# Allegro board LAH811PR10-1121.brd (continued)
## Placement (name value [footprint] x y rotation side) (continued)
R246  150_0201_1%  [R_0201]  100.42 74.4 270 top
R247  0_0201_5%  [R0201_0OHM]  88.25 73.82 90 top
R249  0_0201_5%  [R_0201]  109.69 69.04 270 top
R257  0_0201_5%  [R_0201]  102.15 73.47 90 bottom
R260  0_0201_5%  [R_0201]  98.52 74.4 270 top
R261  1.5K_0201_5%  [R_0201]  99.25 75.13 180 top
R267  1K_0201_5%  [R_0201]  101.56 74.06 270 bottom
R270  1K_0201_5%  [R_0201]  87.82 61.94 90 bottom
R271  75_0201_1%  [R_0201]  194.78 19.96 0 bottom
R272  330K_0201_1%  [R_0201]  226.47 15.79 180 bottom
R273  0_0201_5%  [R0201_0OHM]  226.58 15.21 180 bottom
R274  10K_0201_5%  [R_0201]  107.02 61.37 90 top
R283  1M_0201_5%  [R_0201]  225.97 13.94 90 bottom
R288  100K_0201_5%  [R_0201]  125.97 63.49 90 top
R300  0_0201_5%  [R0201_0OHM]  87.67 73.82 90 top
R311  1K_0201_5%  [R_0201]  103.26 73.47 90 bottom
R312  0_0201_5%  [R0201_0OHM]  90.51 63.23 270 top
R322  100K_0201_5%  [R_0201]  200.4 9.98 90 bottom
R335  0_0201_5%  [R_0201]  93.05 62.64 90 top
R374  100K_0201_5%  [R_0201]  183.73 41.69 90 top
R375  100K_0201_5%  [R_0201]  184.37 41.69 90 top
R390  0_0402_5%  [R_0402]  261.18 42.51 90 bottom
R410  100K_0201_5%  [R_0201]  92.75 59.96 90 bottom
R441  0_0603_5%  [R0603_0OHM]  192.95 40.15 180 bottom
R466  1K_0201_5%  [R_0201]  103.28 65.98 0 bottom
R529  75K_0201_5%  [R_0201]  162.14 6.67 270 top
R530  200_0201_1%  [R_0201]  253.84 23.72 270 bottom
R531  200_0201_1%  [R_0201]  251.93 24.86 180 bottom
R532  75K_0201_5%  [R_0201]  163.82 6.06 90 top
R533  0_0201_5%  [R0201_0OHM]  202.49 14.49 270 bottom
R534  0_0201_5%  [R_0201]  163.67 7.56 0 top
R544  0_0201_5%  [R_0201]  91.15 63.23 270 top
R545  0_0201_5%  [R_0201]  91.15 61.96 270 top
R600  10K_0201_5%  [R_0201]  254.6 50.11 90 bottom
R614  51_0201_5%  [R_0201]  130.9 55.9 90 top
R616  100K_0201_5%  [R_0201]  201.28 11.45 0 bottom
R617  20K_0201_5%  [R_0201]  200.67 11.45 180 bottom
R621  10K_0201_5%  [R_0201]  109.49 70.31 270 bottom
R622  10K_0201_5%  [R_0201]  112.92 68.01 0 bottom
R623  200K_0201_5%  [R_0201]  115.53 68.39 270 bottom
R624  200K_0201_5%  [R_0201]  109.79 68.52 270 bottom
R626  0_0402_5%  [R_0402]  183.1 37.41 315 top
R627  47K_0201_5%  [R_0201]  110.33 69.11 180 bottom
R628  47K_0201_5%  [R_0201]  110.38 68.52 270 bottom
R629  100K_0201_5%  [R_0201]  188.41 3.22 270 top
R633  0_0201_5%  [R0201_0OHM]  90.07 72.94 180 bottom
R634  0_0402_5%  [R_0402]  187.54 45.28 90 top
R638  0_0402_5%  [R0402_0OHM]  260.39 43.43 270 bottom
R644  0_0201_5%  [R_0201]  99.15 74.4 270 top
R648  33_0201_5%  [R_0201]  182.21 30.93 90 bottom
R649  10K_0201_5%  [R_0201]  183.35 41.6 180 bottom
R651  0_0201_5%  [R0201_0OHM]  113.17 70.96 180 bottom
R652  0_0201_5%  [R0201_0OHM]  110.95 66.35 45 bottom
R655  0_0402_5%  [R_0402]  186.78 45.28 90 top
R656  10K_0201_5%  [R_0201]  189.18 37.86 0 bottom
R658  100K_0201_5%  [R_0201]  113.74 70.4 180 bottom
R660  51_0201_5%  [R_0201]  131.66 55.95 90 top
R666  100K_0201_5%  [R_0201]  18.51 43.5 270 bottom
R667  100K_0201_5%  [R_0201]  19.14 43.5 270 bottom
R669  0_0603_5%  [R0603_0OHM]  20.66 38.42 180 bottom
R670  0_0603_5%  [R0603_0OHM]  225.97 17.26 0 bottom
R672  0_0201_5%  [R0201_0OHM]  104.38 68.76 270 bottom
R677  1M_0201_5%  [R_0201]  111.98 71.57 180 bottom
R687  0_0402_5%  [R_0402]  184.56 36.9 90 bottom
R688  0_0402_5%  [R_0402]  184.65 46.45 270 bottom
R700  49.9_0201_1%  [R_0201]  186.91 36.45 270 bottom
R701  49.9_0201_1%  [R_0201]  190.97 36.52 180 bottom
R702  0_0201_5%  [R0201_0OHM]  187.8 37.28 90 bottom
R703  49.9_0201_1%  [R_0201]  181.6 31.31 180 bottom
R704  10K_0201_5%  [R_0201]  187.59 46.78 90 bottom
R716  0_0805_5%  [R0805_0OHM]  255.49 56.08 90 bottom
R725  0_0201_5%  [R_0201]  102.71 74.67 90 bottom
R726  0_0201_5%  [R_0201]  103.26 74.67 90 bottom
R747  0_0201_5%  [R0201_0OHM]  187.62 46.14 270 bottom
R789  150_0201_1%  [R_0201]  218.63 13.45 180 bottom
R800  0_0201_5%  [R0201_0OHM]  272.1 42.51 0 bottom
R801  0_0201_5%  [R_0201]  272.68 43.15 180 bottom
R808  0_0201_5%  [R0201_0OHM]  255.64 37.99 180 bottom
R931  2.1K_0402_1%  [R_0402]  92.42 68.32 180 bottom
R932  2.1K_0402_1%  [R_0402]  92.42 67.53 180 bottom
R1015  0_0201_5%  [R0201_0OHM]  128.36 63.57 90 top
R1016  0_0201_5%  [R0201_0OHM]  129 63.57 90 top
R2745  100K_0201_1%  [R_0201]  199.01 24.33 180 bottom
R2751  0_0402_5%  [R_0402]  195.54 27.7 270 bottom
R5717  0_0603_5%  [R_0603]  183.53 39.4 270 bottom
R5768  10K_0402_5%  [R_0402]  199.99 24.15 270 bottom
R5769  1M_0402_5%~D  [R_0402]  201 20.44 90 bottom
R5779  0_0402_5%  [R0402_0OHM]  199.05 22.67 180 bottom
R5867  270K_0402_5%  [R_0402]  183.38 70.53 90 bottom
R5868  47K_0402_5%  [R_0402]  177.15 68.23 225 bottom
R6048  0_0603_5%  [R0603_0OHM]  185.64 48.52 90 top
R6089  0_0402_5%  [R0402_0OHM]  7.28 42.06 0 bottom
R6090  0_0402_5%  [R0402_0OHM]  7.28 42.88 0 bottom
R6116  0_0201_5%  [R0201_0OHM]  163.67 62.93 90 top
R6117  0_0201_5%  [R0201_0OHM]  163.03 62.93 90 top
R6118  0_0201_5%  [R0201_0OHM]  159.09 61.08 90 bottom
R6137  100K_0201_5%  [R_0201]  202.51 15.16 180 bottom
R6143  1K_0201_5%  [R_0201]  89.88 61.37 90 top
R6157  10K_0201_5%  [R_0201]  159.75 61.51 0 bottom
R6161  0_0603_5%  [R0603_0OHM]  186.88 48.4 135 bottom
R6162  10K_0201_5%  [R_0201]  192.27 45.78 90 bottom
R6163  0_0201_5%  [R0201_0OHM]  191.61 46.7 45 bottom
R6168  0_0201_5%  [R_0201]  103.14 67.77 90 bottom
R6169  0_0201_5%  [R0201_0OHM]  120.79 3.37 270 top
R6170  0_0201_5%  [R0201_0OHM]  197.51 37.43 90 bottom
R6171  0_0201_5%  [R_0201]  19.78 43.5 270 bottom
R6172  4.7K_0201_5%  [R_0201]  167.98 51.63 270 top
R6174  4.7K_0201_5%  [R_0201]  176.78 43.11 180 top
R6181  0_0201_5%  [R0201_0OHM]  26.13 3.12 0 bottom
R6182  0_0603_5%  [R0603_0OHM]  31.62 2.08 0 bottom
R6194  100K_0201_5%  [R_0201]  103.79 67.56 0 bottom
R6199  0_0201_5%  [R0201_0OHM]  220.52 17.39 0 bottom
R6204  100K_0201_5%  [R_0201]  101.89 68.07 90 bottom
R6208  0_0201_5%  [R0201_0OHM]  158.33 61.08 90 bottom
R6211  0_0201_5%  [R0201_0OHM]  209.07 3.68 0 bottom
R6212  100K_0201_5%  [R_0201]  210.43 3.33 90 bottom
R6213  0_0603_5%  [R0603_0OHM]  211.35 9.85 180 bottom
R6214  10K_0201_1%  [R_0201]  205.31 11.78 0 bottom
R6215  2.2K_0201_1%  [R_0201]  196.51 1.59 90 bottom
R6216  2.2K_0201_1%  [R_0201]  196.51 3.38 270 bottom
R6217  4.7K_0201_1%  [R_0201]  195.82 4.96 0 bottom
R6218  4.7K_0201_1%  [R_0201]  196.41 5.85 0 bottom
R6219  0_0201_5%  [R0201_0OHM]  195.35 2.2 0 bottom
R6220  0_0201_5%  [R0201_0OHM]  195.35 2.77 0 bottom
R6222  0_0201_5%  [R_0201]  119.72 5.02 180 top
R6223  0_0201_5%  [R_0201]  166.51 61.07 90 top
R6224  0_0201_5%  [R_0201]  167.12 61.07 90 top
R6225  0_0402_5%  [R_0402]  5.53 41.24 270 top
R6226  0_0402_5%  [R_0402]  5.53 42 90 top
R6227  0_0603_5%  [R0603_0OHM]  233.8 3.12 270 top
R6229  0_0201_5%  [R_0201]  167.78 3.22 90 top
RA1  2.2K_0201_5%  [R_0201]  260.95 67.12 180 top
RA2  2.2K_0201_5%  [R_0201]  262.09 67.51 180 bottom
RA3  20_0201_1%  [R_0201]  262.98 66.24 90 bottom
RA6  20_0201_1%  [R_0201]  262.35 65.22 0 bottom
RA8  1K_0201_5%  [R_0201]  261.33 59.89 90 bottom
RA9  1K_0201_5%  [R_0201]  261.33 62.43 90 bottom
RA10  100K_0201_5%  [R_0201]  255.51 65.35 270 top
RA13  100K_0201_1%  [R_0201]  256.12 57.98 180 top
RA14  200K _0201_1%  [R_0201]  277.72 69.33 180 bottom
RA17  0_0201_5%  [R_0201]  265.39 58.88 270 top
RA21  1K_0201_5%  [R_0201]  265.77 57.07 90 top
RA22  0_0402_5%  [R0402_0OHM]  264.5 61.41 90 bottom
RA23  0_0402_5%  [R0402_0OHM]  269.09 69.47 180 bottom
RA25  0_0402_5%  [R0402_0OHM]  265.39 61.41 90 bottom
RA27  0_0201_5%  [R0201_0OHM]  261.33 61.16 90 bottom
RA28  0_0201_5%  [R0201_0OHM]  261.96 62.43 90 bottom
RA30  1K_0201_5%  [R_0201]  260.69 62.81 270 bottom
RA36  0_0402_5%  [R0402_0OHM]  257.24 54.78 90 top
RA41  0_0402_5%  [R0402_0OHM]  266.87 57.5 90 top
RA57  1K_0201_5%  [R_0201]  257.39 56.46 90 top
RA58  0_0201_5%  [R0201_0OHM]  259.42 56.71 90 top
RA62  22_0201_5%  [R_0201]  260.06 56.71 90 top
RA63  100K_0201_5%  [R_0201]  256.76 56.46 90 top
RA64  10K_0201_5%  [R_0201]  258.79 66.36 90 top
RA71  2.2K_0201_5%  [R_0201]  275.65 34.89 180 top
RA72  2.2K_0201_5%  [R_0201]  275.65 34.26 180 top
RA73  0_0603_5%  [R0603_0OHM]  27.59 27.88 0 top
RA74  0_0603_5%  [R0603_0OHM]  274.66 37.34 90 top
RA75  33_0201_5%  [R_0201]  263.87 57.22 270 top
RA76  33_0201_5%  [R_0201]  263.23 57.22 270 top
RA77  33_0201_5%  [R_0201]  262.6 57.22 270 top
RA78  33_0201_5%  [R_0201]  261.96 55.95 270 top
RA79  4.7K_0201_5%  [R_0201]  26.38 19.5 180 top
RA80  4.7K_0201_5%  [R_0201]  275.65 33.62 180 top
RA81  0_0402_5%  [R_0402]  255.11 59.25 0 bottom
RA82  470_0201_1%  [R_0201]  275.65 32.99 180 top
RA83  4.7K_0201_5%  [R_0201]  27.01 20.48 90 top
RA84  0_0402_5%  [R_0402]  264.53 57.32 270 top
RC1  150_0201_1%  [R_0201]  141.33 61.09 0 bottom
RC2  49.9_0201_1%  [R_0201]  133.5 55.76 90 top
RC3  150_0201_1%  [R_0201]  129.49 58.65 270 top
RC8  100_0201_1%  [R_0201]  118.97 58.91 180 bottom
RC12  100_0201_1%  [R_0201]  125.3 33.25 270 bottom
RC13  100_0201_1%  [R_0201]  125.94 33.25 270 bottom
RC14  100_0201_1%  [R_0201]  123.53 32.33 0 bottom
RC15  150_0201_1%  [R_0201]  168.7 37.53 0 top
RC16  200_0201_1%  [R_0201]  160.61 41.17 90 top
RC17  200_0201_1%  [R_0201]  169.46 46.54 0 top
RC20  200_0201_1%  [R_0201]  156.04 38.2 270 top
RC21  10K_0402_5%  [R_0402]  168.97 8.83 0 top
RC120  0_0603_5%  [R_0603]  175.41 47.5 0 bottom
RC139  0_0603_5%  [R0603_0OHM]  170.47 7.82 180 top
RC145  51_0201_5%  [R_0201]  128.87 57.35 0 top
RC146  51_0201_5%  [R_0201]  125.98 56.21 180 top
RC147  100K_0201_5%  [R_0201]  175.73 53.19 270 top
RC150  100_0201_5%  [R_0201]  128.1 61.06 90 bottom
RC151  51_0201_5%  [R_0201]  127.53 61.06 90 bottom
RC165  0_0402_5%  [R0402_0OHM]  177.32 44.89 180 bottom
RC168  0_0402_5%  [R_0402]  177.32 44.13 180 bottom
RC180  51_0201_5%  [R_0201]  129.49 56.49 270 top
RC181  51_0201_5%  [R_0201]  129.82 61.64 180 bottom
RC201  51_0201_5%  [R_0201]  128.22 56.49 270 top
RC202  100_0201_5%  [R_0201]  125.81 61.06 90 bottom
RC203  51_0201_5%  [R_0201]  128.66 61.05 90 bottom
RC222  49.9K_0201_1%  [R_0201]  172.89 49.72 0 bottom
RC223  49.9K_0201_1%  [R_0201]  172.89 48.58 0 bottom
RC226  0_0201_5%  [R0201_0OHM]  141.29 67.7 180 bottom
RC244  10K_0201_5%  [R_0201]  173.74 57.35 180 top
RC247  1K_0201_5%  [R_0201]  107.02 65.35 270 bottom
RC254  0_0201_5%  [R_0201]  154.69 35.46 90 top
RC255  0_0201_5%  [R0201_0OHM]  155.25 35.84 90 top
RC336  10_0201_1%  [R_0201]  159.31 33.12 270 bottom
RC338  10K_0201_5%  [R_0201]  155.96 35.83 90 top
RC339  10K_0201_5%  [R_0201]  154.13 35.46 90 top
RC344  51_0201_5%  [R_0201]  128.2 58.61 0 top
RC351  0_0201_5%  [R_0201]  142.93 62.92 0 bottom
RC367  10_0201_1%  [R_0201]  157.64 33.12 270 bottom
RC368  10_0201_1%  [R_0201]  158.2 33.12 270 bottom
RC369  10_0201_1%  [R_0201]  158.76 33.12 270 bottom
RC430  0_0201_5%  [R0201_0OHM]  173.19 55.44 90 top
RC432  1K_0201_5%  [R_0201]  173.74 56.71 180 top
RC433  8.2K_0201_5%  [R_0201]  170.02 56.08 270 top
RC434  8.2K_0201_5%  [R_0201]  170.02 54.3 90 top
RC503  22_0201_1%  [R_0201]  253.63 10.83 90 top
RC504  22_0201_1%  [R_0201]  257 10.81 0 top
RC505  0_0402_5%  [R0402_0OHM]  174.28 29.53 180 bottom
RC508  1M_0201_5%  [R_0201]  172.68 29.57 270 bottom
RC569  49.9_0201_1%  [R_0201]  158.45 33.25 90 top
RC582  0_0402_5%  [R_0402]  173.94 46.61 180 top
RC583  0_0402_5%  [R0402_0OHM]  172.1 46.99 270 top
RC587  0_0603_5%  [R_0603]  177.95 50.16 270 bottom
RC589  0.1_0402_1%  [R_0402]  174.45 47.74 270 bottom
RC592  0_0603_5%  [R0603_0OHM]  154.01 62.93 0 top
RC595  100K_0201_5%  [R_0201]  166.36 52.13 180 top
RC601  0_0201_5%  [R0201_0OHM]  114.52 58.11 0 bottom
RC602  56_0201_5%  [R_0201]  112.99 58.11 0 bottom
RC603  0_0201_5%  [R0201_0OHM]  114.52 57.47 0 bottom
RC604  100_0201_1%  [R_0201]  113 57.47 0 bottom
RC605  0_0201_5%  [R0201_0OHM]  114.52 58.74 0 bottom
RC606  100_0201_5%  [R_0201]  113 58.74 0 bottom
RC609  10K_0201_5%  [R_0201]  180.3 42.05 180 bottom
RC610  10K_0201_5%  [R_0201]  180.3 41.42 180 bottom
RC611  10K_0201_5%  [R_0201]  180.3 42.72 180 bottom
RC612  10K_0201_5%  [R_0201]  180.3 40.71 180 bottom
RC614  499_0201_1%  [R_0201]  121.93 56.46 0 top
RC615  100K_0201_5%  [R_0201]  180.76 51.12 180 bottom
RC616  100K_0201_5%  [R_0201]  177.76 52.39 90 bottom
RC617  100K_0201_5%  [R_0201]  178.91 51.12 0 bottom
RC619  0_0201_5%  [R_0201]  180.94 47.44 180 bottom
RC623  0_0201_5%  [R_0201]  181.32 49.73 270 top
RC624  0_0201_5%  [R0201_0OHM]  179.72 43.29 0 bottom
RC626  100K_0201_5%  [R_0201]  181.32 48.46 270 top
RC627  0_0201_5%  [R0201_0OHM]  180.99 43.78 0 bottom
RC630  0_0603_5%  [R0603_0OHM]  151.6 62.93 0 top
RC631  100K_0201_5%  [R_0201]  142.5 67.7 180 bottom
RC634  0_0201_5%  [R_0201]  144.79 61.59 0 top
RC636  0_0201_5%  [R_0201]  146.78 63.82 270 top
RC639  0_0603_5%  [R0603_0OHM]  149.38 63.38 0 bottom
RC640  0_0201_5%  [R0201_0OHM]  148.93 33.25 270 bottom
RC643  0_0603_5%  [R0603_0OHM]  152.11 30.36 90 bottom
RC644  0_0201_5%  [R_0201]  107.02 66.62 270 bottom
RC647  1K_0201_5%  [R_0201]  108.29 64.58 180 bottom
RC648  100K_0201_5%  [R_0201]  161.2 42.92 270 top
RC651  0_0201_5%  [R0201_0OHM]  183.73 42.96 90 top
RC655  49.9K_0201_1%  [R_0201]  172.89 48 0 bottom
RC656  49.9K_0201_1%  [R_0201]  172.89 49.15 0 bottom
RC657  0_0201_5%  [R0201_0OHM]  184.37 42.96 90 top
RC659  0_0603_5%  [R0603_0OHM]  119.57 58.44 270 top
RC663  10K_0201_5%  [R_0201]  183.27 40.23 0 bottom
RC664  10K_0201_5%  [R_0201]  180.91 41.61 270 bottom
RC667  1K_0201_5%  [R_0201]  158.59 37.62 90 top
RC668  1K_0201_5%  [R_0201]  157.95 37.62 90 top
RC671  10K_0201_5%  [R_0201]  166.15 47.75 90 top
RC672  1K_0201_5%  [R_0201]  175.47 43.04 180 bottom
RC673  1K_0201_5%  [R_0201]  175.47 42.48 180 bottom
RC682  10K_0201_5%  [R_0201]  155.4 33.42 90 top
RC683  0_0201_5%  [R0201_0OHM]  119.05 53.56 180 top
RC684  0_0201_5%  [R0201_0OHM]  119.06 54.14 180 top
RC685  0_0201_5%  [R0201_0OHM]  134.64 61.62 270 bottom
RC686  0_0201_5%  [R0201_0OHM]  134.07 61.62 270 bottom
RC687  10K_0201_5%  [R_0201]  157.31 39.65 90 top
RC688  0_0201_5%  [R0201_0OHM]  176.14 40.76 0 bottom
RC689  0_0201_5%  [R0201_0OHM]  155.4 40.89 0 top
RC690  0_0201_5%  [R0201_0OHM]  174.9 41.34 0 bottom
RC691  20K_0201_5%  [R_0201]  168.62 51.63 270 top
RC693  20K_0201_5%  [R_0201]  176.78 42.48 180 top
RC695  0_0201_5%  [R0201_0OHM]  192.09 22.9 180 bottom
RC696  0_0402_5%  [R0402_0OHM]  174.25 42.99 0 top
RC697  0_0201_5%  [R0201_0OHM]  175.06 28.9 0 bottom
RC698  0_0201_5%  [R_0201]  174.33 30.29 180 bottom
RC699  0_0201_5%  [R0201_0OHM]  173.06 30.96 270 bottom
RC700  100K_0201_5%  [R_0201]  181.19 47.19 180 top
RC701  100K_0201_5%  [R_0201]  146.14 63.82 270 top
RC702  0_0201_5%  [R0201_0OHM]  101.25 68.66 270 bottom
RC703  0_0201_5%  [R0201_0OHM]  100.62 68.66 270 bottom
RC704  0_0201_5%  [R0201_0OHM]  102.52 68.66 270 bottom
RC711  75K_0201_1%  [R_0201]  159.87 33.12 270 bottom
RC712  75K_0201_1%  [R_0201]  160.51 33.12 270 bottom
RC717  10K_0201_5%  [R_0201]  150.33 32.63 90 bottom
RC718  0_0603_5%  [R0603_0OHM]  143.85 61.78 0 bottom
RC723  10K_0201_5%  [R_0201]  130.05 55.32 270 top
RC724  10K_0201_5%  [R_0201]  130.05 55.9 90 top
RC727  0_0201_5%  [R_0201]  172.84 42.82 0 bottom
RC730  0_0201_5%  [R_0201]  142.84 64.2 90 top
RC731  0_0201_5%  [R0201_0OHM]  142.84 65.98 270 top
RC734  33_0201_5%  [R_0201]  162.13 38.58 90 top
RC735  100K_0201_5%  [R_0201]  180.32 43.88 180 bottom
RC736  0_0402_5%  [R_0402]  195.39 21.76 270 bottom
RC737  1M_0201_5%  [R_0201]  194.7 20.85 180 bottom
RC738  10K_0201_5%  [R_0201]  181.57 43.22 180 bottom
RC739  10K_0201_5%  [R_0201]  183.45 43.4 270 bottom
RC741  10K_0201_5%  [R_0201]  182.16 43.78 0 bottom
RC742  10K_0201_5%  [R_0201]  182.16 43.22 0 bottom
RC744  20K_0201_5%  [R_0201]  182.1 39.7 315 bottom
RC745  0_0402_5%  [R0402_0OHM]  186.37 28.16 0 top
RC746  0_0201_5%  [R_0201]  177.91 46.2 270 bottom
RC747  0_0402_5%  [R0402_0OHM]  163.95 40 0 top
RC748  10K_0201_5%  [R_0201]  163.29 61.03 90 bottom
RC749  10K_0201_5%  [R_0201]  162.65 61.03 90 bottom
RC750  10K_0201_5%  [R_0201]  174.85 37.84 180 bottom
RC751  10K_0201_5%  [R_0201]  174.66 38.4 180 bottom
RC782  100_0402_1%  [R_0402]  192.6 74.5 270 bottom
RC783  100K_0201_5%  [R_0201]  188.12 72.66 45 bottom
RD1  240_0201_1%  [R_0201]  162.81 27.33 270 top
RD2  240_0201_1%  [R_0201]  160.33 27.44 270 top
RD3  240_0201_1%  [R_0201]  131.44 27.33 270 top
RD4  240_0201_1%  [R_0201]  128.36 27.37 270 top
RD21  240_0201_1%  [R_0201]  146.55 27.46 270 top
RD22  240_0201_1%  [R_0201]  149.32 27.37 270 top
RD23  240_0201_1%  [R_0201]  114.8 27.33 270 top
RD24  240_0201_1%  [R_0201]  117.29 27.38 270 top
RD25  0_0201_5%  [R0201_0OHM]  155.11 18.45 180 top
RD26  0_0201_5%  [R_0201]  155.11 19.09 180 top
RD27  0_0201_5%  [R0201_0OHM]  155.11 15.5 180 top
RD28  0_0201_5%  [R_0201]  155.11 14.89 180 top
RD29  0_0201_5%  [R0201_0OHM]  141.4 19.59 180 top
RD30  0_0201_5%  [R_0201]  141.4 20.23 180 top
RD31  0_0201_5%  [R0201_0OHM]  141.52 15.47 180 top
RD32  0_0201_5%  [R_0201]  141.52 14.83 180 top
RD33  0_0201_5%  [R0201_0OHM]  123.11 20.93 180 top
RD34  0_0201_5%  [R_0201]  123.11 21.56 180 top
RD35  0_0201_5%  [R0201_0OHM]  123.11 15.02 180 top
RD36  0_0201_5%  [R_0201]  123.11 14.45 180 top
RD37  0_0201_5%  [R0201_0OHM]  108.81 20.86 0 top
RD38  0_0201_5%  [R_0201]  109.39 21.5 180 top
RD39  0_0201_5%  [R0201_0OHM]  108.81 16.04 0 top
RD40  0_0201_5%  [R_0201]  109.39 15.4 180 top
RD41  100K_0402_5%  [R_0402]  204.2 45.99 270 top
RD42  100K_0402_5%  [R_0402]  102.2 14.17 180 bottom
RD43  0_0402_5%  [R_0402]  199.1 48.91 270 bottom
RD44  0_0201_5%  [R_0201]  200.59 48.71 180 bottom
RD45  0_1206_5%  [R_1206]  171.04 27.73 180 top
RD46  0_1206_5%  [R_1206]  103.8 24.27 270 bottom
RD47  0.1_0402_1%  [R_0402]  199.48 40.66 90 bottom
RD48  200K_0402_1%  [R_0402]  217.41 14.29 0 bottom
RD300  1M_0201_5%  [R_0201]  200.41 47.31 180 bottom
RD400  0_0402_5%  [R0402_0OHM]  199.84 48.01 0 bottom
RE1  10K_0201_5%  [R_0201]  174.62 11.72 180 top
RE10  0_0201_5%  [R_0201]  109.95 58.95 180 bottom
RE14  100K_0201_5%  [R_0201]  195.54 25.76 270 bottom
RE15  0_0201_5%  [R_0201]  192.24 25.72 90 bottom
RE21  100K_0201_5%  [R_0201]  195.9 22.45 90 bottom
RE22  0_0201_5%  [R_0201]  195.29 23.03 270 bottom
RE29  100K_0201_5%  [R_0201]  108.68 58.95 180 bottom
RE48  100K_0201_5%  [R_0201]  180.68 9.47 270 top
RE49  0_0603_5%  [R0603_0OHM]  172.55 15.47 90 top
RE87  100K_0201_5%  [R_0201]  152.4 29.58 180 bottom
RE93  10K_0201_5%  [R_0201]  155.88 31.84 0 bottom
RE95  100K_0201_5%  [R_0201]  172.76 20.49 0 top
RE96  100K_0201_5%  [R_0201]  189.22 11.98 180 top
RE97  100K_0201_5%  [R_0201]  173.88 14.93 0 top
RE98  100K_0201_5%  [R_0201]  190.89 24.33 180 top
RE99  100K_0201_5%  [R_0201]  190.93 17.32 180 top
RE100  100K_0201_5%  [R_0201]  190.93 19.37 180 top
RE101  100K_0201_5%  [R_0201]  190.92 20.62 180 top
RE102  100K_0201_5%  [R_0201]  190.91 22.8 180 top
RE106  0_0402_5%  [R0402_0OHM]  179.26 25.42 180 top
RE108  100K_0201_5%  [R_0201]  190.35 18.74 0 top
RE109  100K_0201_5%  [R_0201]  190.34 16.71 0 top
RE111  2.2K_0201_5%  [R_0201]  177.37 10.74 270 top
RE112  2.2K_0201_5%  [R_0201]  176.74 10.74 270 top
RE113  100_0201_5%  [R_0201]  172.8 18.67 90 top
RE115  43K_0402_1%  [R_0402]  178.14 9.85 90 top
RE122  100K_0201_5%  [R_0201]  187.13 10.16 90 top
RE124  10K_0201_1%  [R_0201]  190.31 23.69 0 top
RE125  300_0402_5%  [R_0402]  179.08 9.03 270 top
RE126  300_0402_5%  [R_0402]  179.03 10.78 270 top
RE130  100K_0201_5%  [R_0201]  190.92 21.91 180 top
RE133  100K_0201_5%  [R_0201]  173.35 21.12 180 top
RE137  100K_0201_5%  [R_0201]  180.47 24.71 90 top
RE142  100K_0201_5%  [R_0201]  179.91 24.71 90 top
RE147  0_0201_5%  [R0201_0OHM]  187.14 9.49 270 top
RE152  1K_0201_5%  [R_0201]  170.05 21.25 0 top
RE153  43_0402_5%  [R_0402]  188.6 13.94 0 top
RE154  100K_0201_5%  [R_0201]  172.08 21.25 180 top
RE156  100K_0201_5%  [R_0201]  188.64 10.17 0 top
RE157  100K_0201_5%  [R_0201]  170.96 16.88 0 top
RE158  100_0402_1%  [R_0402]  188.6 16.68 0 top
RE159  10K_0201_5%  [R_0201]  180.68 10.74 270 top
RE160  100K_0201_5%  [R_0201]  174.03 12.48 0 top
RE164  100_0201_1%  [R_0201]  189.15 7.15 0 top
RE172  33_0201_5%  [R_0201]  170.6 23.51 180 top
RE178  0_0402_5%  [R_0402]  177.38 25.16 180 top
RE184  100K_0201_5%  [R_0201]  171.49 20.69 0 top
RE185  0_0201_5%  [R0201_0OHM]  188.64 10.76 0 top
RE186  0_0201_5%  [R_0201]  174.03 14.01 0 top
RE187  1K_0201_5%  [R_0201]  171.49 20.1 0 top
RE193  0_0201_5%  [R_0201]  153.48 7.18 0 top
RE194  8.2K_0201_1%  [R_0201]  189.82 15.38 180 top
RE199  1.58K_0402_1%  [R_0402]  188.55 23.41 0 top
RE200  10_0201_1%  [R_0201]  237.63 12.58 270 bottom
RE201  10K_0201_5%  [R_0201]  240.83 11.99 90 bottom
RE202  10K_0201_5%  [R_0201]  242.88 11.24 0 bottom
RE203  10K_0201_5%  [R_0201]  242.88 10.66 0 bottom
RE204  100K_0201_5%  [R_0201]  242.7 12.01 180 bottom
RE205  10K_0201_5%  [R_0201]  241.42 12.58 270 bottom
RE206  0_0201_5%  [R_0201]  243.63 12.12 90 bottom
RE208  100K_0201_5%  [R_0201]  189.22 12.61 180 top
RE209  0_0201_5%  [R0201_0OHM]  242.11 12.64 0 bottom
RE210  10K_0201_5%  [R_0201]  240.17 12.58 270 bottom
RE211  10K_0201_5%  [R_0201]  239.54 12.58 270 bottom
RE212  10K_0201_5%  [R_0201]  238.9 12.58 270 bottom
RE213  10K_0201_5%  [R_0201]  238.27 12.58 270 bottom
RE215  8.2K_0201_1%  [R_0201]  162.83 28.86 0 bottom
RE219  2.2K_0201_5%  [R_0201]  158.84 30.54 90 bottom
RE237  100K_0201_5%  [R_0201]  191.26 5.5 0 top
RE244  100K_0201_5%  [R_0201]  181.03 24.71 90 top
RE245  0_0201_5%  [R_0201]  183.7 10.74 270 top
RE247  100K_0201_5%  [R_0201]  174.03 21.12 0 top
RE248  0_0201_5%  [R0201_0OHM]  184.6 28.78 270 top
RE305  0_0402_5%  [R0402_0OHM]  164.66 3.09 270 top
RE312  1M_0201_5%  [R_0201]  164.47 3.8 180 top
RE321  0_0201_1%  [R_0201]  201.87 12.03 180 bottom
RE322  0_0201_1%  [R_0201]  200.09 12.03 0 bottom
RE405  0_0402_5%  [R0402_0OHM]  26.89 21.53 270 bottom
RE411  0_0402_5%  [R0402_0OHM]  184.72 6.84 90 top
RE417  0_0402_5%  [R0402_0OHM]  274.23 15.31 90 top
RE426  100K_0201_5%  [R_0201]  181.22 8.07 270 top
RE428  0_0201_5%  [R0201_0OHM]  155.33 7.18 180 top
RE445  2.2K_0201_5%  [R_0201]  183.14 28.52 0 top
RE446  2.2K_0201_5%  [R_0201]  184.62 31.31 180 top
RE448  0_0201_5%  [R0201_0OHM]  176.04 10.74 270 top
RE449  100K_0201_5%  [R_0201]  206.21 14 90 bottom
RE458  2.2K_0201_5%  [R_0201]  176.11 26.87 90 top
RE459  2.2K_0201_5%  [R_0201]  176.74 26.86 90 top
RE460  0_0201_5%  [R_0201]  194.27 24.66 0 bottom
RE461  0_0201_5%  [R0201_0OHM]  183.11 10.74 270 top
RE462  0_0201_5%  [R0201_0OHM]  182.5 29.53 180 top
RE463  0_0201_5%  [R0201_0OHM]  184.6 30.05 270 top
RE464  0_0201_5%  [R0201_0OHM]  172.42 10.41 90 top
RE467  0_0201_5%  [R0201_0OHM]  189.09 21 180 top
RE468  0_0201_5%  [R0201_0OHM]  189.09 21.64 180 top
RE469  100K_0201_5%  [R_0201]  182.36 7.92 270 top
RE470  100K_0201_5%  [R_0201]  190.34 20.01 0 top
RE471  0_0201_5%  [R0201_0OHM]  189.22 13.25 180 top
RE472  100K_0201_5%  [R_0201]  181.26 10.16 90 top
RE473  100K_0201_5%  [R_0201]  182.53 10.16 90 top
RE475  100K_0201_5%  [R_0201]  189.23 19.25 180 top
RE476  0_0201_5%  [R0201_0OHM]  186.55 10.15 90 top
RE477  0_0201_5%  [R0201_0OHM]  158.84 29.34 90 bottom
RE478  100K_0201_1%  [R_0201]  184.82 6.16 270 top
RE479  390K_0402_1%  [R_0402]  183.66 9.49 270 top
RE480  1M_0201_1%  [R_0201]  188.27 4.99 90 top
RE481  10K_0201_5%  [R_0201]  188.64 11.34 0 top
RE482  0_0201_5%  [R0201_0OHM]  187.72 10.15 90 top
RE483  2.2K_0201_5%  [R_0201]  181.88 4.46 270 top
RE484  2.2K_0201_5%  [R_0201]  182.44 4.46 270 top
RE486  0_0201_5%  [R_0201]  174.03 20.49 0 top
RE487  0_0201_5%  [R_0201]  174.62 13.2 180 top
RE488  100K_0201_5%  [R_0201]  4.43 42.73 0 bottom
RE489  0_0402_5%  [R0402_0OHM]  108.68 58.18 0 bottom
RE492  0_0201_5%  [R0201_0OHM]  190.34 21.27 0 top
RE493  10K_0201_5%  [R_0201]  181.8 7.92 270 top
RE520  100K_0201_1%  [R_0201]  211.6 16.45 90 bottom
RE521  100K_0201_5%  [R_0201]  194.39 4.03 180 top
RE522  100K_0201_5%  [R_0201]  180.64 8.06 270 top
RE525  100K_0201_5%  [R_0201]  173.58 3.9 180 top
RE526  2.2K_0201_5%  [R_0201]  177.38 27.41 270 top
RE527  2.2K_0201_5%  [R_0201]  178.02 27.41 270 top
RE528  100K_0201_5%  [R_0201]  188.08 25.77 0 top
RE530  240K_0402_5%  [R_0402]  170.22 17.16 90 top
RE531  0_0402_5%  [R_0402]  171.44 13.4 180 top
RE534  0_0201_5%  [R_0201]  183.02 4.46 270 top
RE535  0_0201_5%  [R_0201]  181.29 4.46 270 top
RH1  100_0201_1%  [R_0201]  167.1 61.03 359.8 bottom
RH4  49.9_0201_1%  [R_0201]  156.04 39.65 90 top
RH5  49.9_0201_1%  [R_0201]  173.95 57.85 0 bottom
RH6  49.9_0201_1%  [R_0201]  121.85 53.42 90 top
RH7  49.9_0201_1%  [R_0201]  122.62 53.41 90 top
RH8  10K_0201_5%  [R_0201]  165.19 61.03 180 bottom
RH9  10K_0201_5%  [R_0201]  167.22 54.13 90 top
RH10  113_0201_1%  [R_0201]  166.46 61.03 180 bottom
RH11  0_0201_5%  [R0201_0OHM]  143.72 33.03 270 bottom
RH12  470_0201_1%  [R_0201]  108.81 20.23 0 top
RH13  0_0201_5%  [R0201_0OHM]  127.72 32.54 90 bottom
RH14  0_0201_5%  [R_0201]  173.4 55.46 0 bottom
RH15  0_0201_5%  [R_0201]  173.41 54.87 0 bottom
RH16  10M_0201_1%  [R_0201]  167.76 31.88 180 bottom
RH17  200K _0201_1%  [R_0201]  174.59 54.87 90 bottom
RH23  49.9_0201_1%  [R_0201]  188.05 35.93 90 bottom
RH24  49.9_0201_1%  [R_0201]  181.62 29.43 90 bottom
RH25  49.9_0201_1%  [R_0201]  189.96 37.15 0 bottom
RH26  49.9_0201_1%  [R_0201]  191.61 28.05 270 bottom
RH27  49.9_0201_1%  [R_0201]  192.5 30.89 90 bottom
RH39  10K_0201_5%  [R_0201]  176.49 40.58 180 top
RH40  10K_0201_5%  [R_0201]  178.05 43.11 180 top
RH42  0_0201_5%  [R0201_0OHM]  165.55 8.37 180 top
RH46  100K_0201_5%  [R_0201]  181.83 27.08 90 top
RH57  0_0201_5%  [R0201_0OHM]  161.12 37.91 270 top
RH64  1M_0201_1%  [R_0201]  168.7 36.89 0 top
RH80  49.9_0201_1%  [R_0201]  125.24 61.06 90 bottom
RH95  1K_0201_1%  [R_0201]  118.96 59.5 180 bottom
RH96  1K_0201_5%  [R_0201]  121.25 57.09 180 top
RH98  20K_0201_5%  [R_0201]  170.45 49.02 270 top
RH111  33_0201_1%  [R_0201]  159.78 35.08 90 top
RH112  33_0201_1%  [R_0201]  160.36 33.81 90 top
RH113  33_0201_1%  [R_0201]  159.75 33.81 90 top
RH114  75K_0201_5%  [R_0201]  258.89 13.99 90 top
RH129  10K_0201_5%  [R_0201]  176.65 46.04 180 top
RH139  10K_0201_5%  [R_0201]  174.79 45.35 180 top
RH141  100K_0201_5%  [R_0201]  165.05 37.95 270 top
RH142  4.7K_0201_5%  [R_0201]  164.45 37.95 270 top
RH143  499_0201_1%  [R_0201]  177.91 47.37 0 bottom
RH144  499_0201_1%  [R_0201]  177.91 46.8 0 bottom
RH145  10K_0201_5%  [R_0201]  176.65 45.38 180 top
RH185  10K_0201_5%  [R_0201]  173.02 45.35 0 top
RH207  0_0201_5%  [R0201_0OHM]  172.81 39.06 0 bottom
RH217  1K_0201_1%  [R_0201]  160.99 33.81 90 top
RH218  0_0201_5%  [R0201_0OHM]  160.97 32.54 90 top
RH280  0_0201_5%  [R0201_0OHM]  172.81 40.33 0 bottom
RH297  10K_0201_5%  [R_0201]  162.36 32.69 90 bottom
RH298  100K_0201_5%  [R_0201]  169.38 29.44 270 bottom
RH300  10K_0201_5%  [R_0201]  168.99 49.59 270 top
RH301  4.7K_0201_5%  [R_0201]  170.02 29.44 270 bottom
RH312  0_0201_5%  [R0201_0OHM]  161.79 33.27 270 bottom
RH460  100K_0201_5%  [R_0201]  165.03 33.2 270 bottom
RH475  60.4_0201_1%  [R_0201]  173.95 57.09 0 bottom
RH565  0_0402_5%  [R0402_0OHM]  177.25 3.89 0 top
RH572  20K_0201_5%  [R_0201]  174.33 32.83 270 bottom
RH573  20K_0201_5%  [R_0201]  170.01 33.55 90 top
RH575  1M_0201_1%  [R_0201]  178.78 29.91 90 bottom
RH584  0_0201_5%  [R0201_0OHM]  154.47 61.05 90 bottom
RH586  0_0201_5%  [R0201_0OHM]  153.89 61.05 90 bottom
RH587  60.4_0201_1%  [R_0201]  108.95 62.48 180 bottom
RH588  1K_0201_5%  [R_0201]  108.37 63.06 0 bottom
RH591  100K_0201_5%  [R_0201]  163.89 33.2 270 bottom
RH592  10K_0201_5%  [R_0201]  164.46 33.2 270 bottom
RH594  0_0201_5%  [R0201_0OHM]  168.96 50.37 0 top
RH600  0_0201_5%  [R0201_0OHM]  163.53 34.44 90 top
RH601  10K_0201_5%  [R_0201]  162.64 35.03 270 top
RH603  10K_0201_5%  [R_0201]  159.47 39.65 90 top
RH604  10K_0201_5%  [R_0201]  173.44 52.14 0 bottom
RH605  10K_0201_5%  [R_0201]  159.47 37.59 90 top
RH606  1K_0201_5%  [R_0201]  168.36 48.32 270 top
RH607  1K_0201_5%  [R_0201]  166.71 48.32 270 top
RH612  10K_0201_5%  [R_0201]  178.05 46.04 180 top
RH613  10K_0201_5%  [R_0201]  174.2 45.92 0 top
RH614  10K_0201_5%  [R_0201]  178.06 45.41 180 top
RH615  10K_0201_5%  [R_0201]  173.6 45.92 180 top
RH616  10K_0201_5%  [R_0201]  178.06 44.77 180 top
RH617  20K_0201_5%  [R_0201]  165.65 40.97 0 top
RH618  2.2K_0201_5%  [R_0201]  165.65 40.34 0 top
RH621  4.7K_0201_5%  [R_0201]  150.97 33.22 270 bottom
RH622  0_0201_5%  [R0201_0OHM]  129.63 63.57 90 top
RH625  0_0201_5%  [R0201_0OHM]  173.06 28.9 180 top
RH629  10K_0201_5%  [R_0201]  173.45 52.79 0 bottom
RH630  10K_0201_5%  [R_0201]  173.45 53.38 0 bottom
RH631  10K_0201_5%  [R_0201]  177.26 41.6 180 top
RH634  1K_0201_5%  [R_0201]  165.03 38.86 180 top
RH635  100K_0201_5%  [R_0201]  161.88 40.41 90 top
RH636  100K_0201_5%  [R_0201]  162.51 40.41 90 top
RH637  0_0201_5%  [R_0201]  166.54 31.3 0 bottom
RH640  1K_0201_5%  [R_0201]  163.15 37.36 90 top
RH641  4.7K_0201_5%  [R_0201]  163.89 37.82 270 top
RH643  100K_0201_5%  [R_0201]  161.88 37.95 270 top
RH645  0_0201_5%  [R0201_0OHM]  156.04 34.01 270 top
RH646  100K_0201_5%  [R_0201]  169.63 47.75 90 top
RH647  4.7K_0201_5%  [R_0201]  155.99 32.76 180 top
RH653  1K_0201_5%  [R_0201]  173.45 38.42 180 bottom
RH654  0_0201_5%  [R_0201]  172.39 52.27 0 top
RH655  100K_0201_5%  [R_0201]  172.3 50.49 270 top
RH660  100K_0201_5%  [R_0201]  176.24 52.77 270 bottom
RH661  4.7K_0201_5%  [R_0201]  175.6 52.77 270 bottom
RH665  10K_0201_5%  [R_0201]  176.5 44.51 180 top
RH666  4.7K_0201_5%  [R_0201]  171.03 49.01 270 top
RH667  8.2K_0201_5%  [R_0201]  155.4 37.62 90 top
RH671  10K_0201_1%  [R_0201]  173.7 31.56 270 bottom
RH672  10K_0201_5%  [R_0201]  160.36 39.65 90 top
RH675  100K_0201_5%  [R_0201]  173.45 53.97 0 bottom
RH682  100K_0201_5%  [R_0201]  170.2 30.38 90 bottom
RH683  100K_0201_5%  [R_0201]  170.77 30.38 90 bottom
RH684  100K_0201_5%  [R_0201]  169.56 30.38 90 bottom
RH685  100K_0201_5%  [R_0201]  171.91 30.38 90 bottom
RH686  100K_0201_5%  [R_0201]  172.48 30.38 90 bottom
RH687  100K_0201_5%  [R_0201]  162.72 39.16 270 top
RH688  100K_0201_5%  [R_0201]  159.19 33.81 90 top
RH689  100K_0201_5%  [R_0201]  157.31 38.2 270 top
RH690  100K_0201_5%  [R_0201]  157.65 31.84 180 bottom
RH691  100K_0201_5%  [R_0201]  171.34 30.38 90 bottom
RH692  4.7K_0201_5%  [R_0201]  167.72 47.09 270 top
RH705  33_0201_5%  [R_0201]  168.37 41.98 0 top
RH706  33_0201_5%  [R_0201]  168.37 41.34 0 top
RH709  100K_0201_5%  [R_0201]  156.67 38.2 270 top
RH713  100K_0201_5%  [R_0201]  169.63 49.59 270 top
RH714  0_0201_5%  [R_0201]  172.81 39.69 0 bottom
RH715  0_0201_5%  [R_0201]  161.08 32.56 90 bottom
RH716  0_0201_5%  [R_0201]  163.87 41.08 0 top
RH717  100K_0201_5%  [R_0201]  161.24 40.41 90 top
RH718  100K_0201_5%  [R_0201]  158.58 39.65 90 top
RH719  4.99_0201_1%  [R_0201]  181.6 30.6 180 bottom
RH720  4.99_0201_1%  [R_0201]  187.49 36.47 270 bottom
RH721  4.99_0201_1%  [R_0201]  190.92 35.88 180 bottom
RH722  4.99_0201_1%  [R_0201]  190.97 27.46 90 bottom
RH723  4.99_0201_1%  [R_0201]  192.5 32.16 90 bottom
RH724  20K_0201_5%  [R_0201]  256.4 11.49 90 top
RH725  20K_0201_5%  [R_0201]  254.24 11.44 90 top
RH727  10K_0201_5%  [R_0201]  176.06 28.14 0 top
RH728  10K_0201_5%  [R_0201]  265.01 18.74 0 bottom
RH729  0_0201_5%  [R0201_0OHM]  167.6 32.2 0 top
RH732  0_0201_5%  [R_0201]  166.54 49.65 0 top
RH733  100K_0201_5%  [R_0201]  173.7 28.9 0 top
RH735  0_0201_5%  [R0201_0OHM]  192.37 35.88 180 bottom
RH736  0_0201_5%  [R0201_0OHM]  192.5 34.55 90 bottom
RH738  100K_0201_5%  [R_0201]  153.94 33.11 0 top
RH739  100K_0201_5%  [R_0201]  153.94 33.76 0 top
RH740  100K_0201_5%  [R_0201]  152.74 33.11 0 top
RH741  100K_0201_5%  [R_0201]  152.74 33.76 0 top
RH742  10K_0201_5%  [R_0201]  157.94 39.65 90 top
RH743  0_0201_5%  [R_0201]  174.59 50.49 180 top
RH744  0_0201_5%  [R0201_0OHM]  172.3 53.03 0 top
RH745  100K_0201_5%  [R_0201]  151.6 33.22 270 bottom
RH746  100K_0201_5%  [R_0201]  149.7 33.22 270 bottom
RH747  100K_0201_5%  [R_0201]  156.02 61.04 0 bottom
RH748  100K_0201_5%  [R_0201]  264.17 5.02 90 bottom
RH749  75K_0201_5%  [R_0201]  167.53 47.72 90 top
RH750  0_0201_5%  [R_0201]  165.03 66.21 0 top
RH751  0_0201_5%  [R_0201]  162.28 31.31 180 top
RM1  0_0201_5%  [R0201_0OHM]  29 62.82 90 top
RM2  0_0201_5%  [R0201_0OHM]  34.5 65.27 180 top
RM9  0_0201_5%  [R0201_0OHM]  33.92 64.64 0 top
RM10  0_0201_5%  [R0201_0OHM]  29.64 63.41 270 top
RM11  0_0201_5%  [R0201_0OHM]  278.03 53.84 270 bottom
RM12  0_0201_5%  [R0201_0OHM]  280.57 53.84 270 bottom
RM13  0_0201_5%  [R0201_0OHM]  34.5 64 180 top
RM14  0_0201_5%  [R0201_0OHM]  30.27 62.82 90 top
RM15  0_0201_5%  [R0201_0OHM]  278.66 53.26 90 bottom
RM16  0_0201_5%  [R0201_0OHM]  279.93 53.26 90 bottom
RM17  0_0201_5%  [R0201_0OHM]  281.2 53.26 90 bottom
RM18  0_0201_5%  [R0201_0OHM]  277.39 53.26 90 bottom
RM19  0_0201_5%  [R0201_0OHM]  33.92 66.54 0 top
RM20  0_0201_5%  [R0201_0OHM]  33.92 65.91 0 top
RM21  0_0201_5%  [R0201_0OHM]  276.1 56.28 180 bottom
RM22  0_0201_5%  [R0201_0OHM]  276.1 55.71 180 bottom
RPD11  3.3K_0201_5%  [R_0201]  38.32 50.36 90 bottom
RPD12  3.3K_0201_5%  [R_0201]  37.05 50.36 90 bottom
RPD13  3.3K_0201_5%  [R_0201]  37.56 61.03 180 bottom
RPD14  3.3K_0201_5%  [R_0201]  35.78 50.36 90 bottom
RPD17  0_0201_5%  [R0201_0OHM]  24.33 41.4 90 bottom
RPD21  0_0201_5%  [R0201_0OHM]  25.85 41.39 90 bottom
RPD22  0_0201_5%  [R0201_0OHM]  26.48 41.39 90 bottom
RPD59  3.3K_0201_5%  [R_0201]  249.31 12.01 90 bottom
RPD60  3.3K_0201_5%  [R_0201]  248.04 12.01 90 bottom
RPD61  3.3K_0201_5%  [R_0201]  248.67 23.31 180 bottom
RPD62  3.3K_0201_5%  [R_0201]  246.8 12.01 90 bottom
RPD84  0_0402_5%  [R0402_0OHM]  29.02 28.08 90 bottom
RPD88  0_0201_5%  [R0201_0OHM]  33.05 38.76 0 bottom
RPD89  10K_0201_1%  [R_0201]  267.56 32.99 0 top
RPD90  100K_0201_1%  [R_0201]  22.26 31.28 0 bottom
RPD91  300K_0201_1%  [R_0201]  27.82 28.26 270 bottom
RPD92  100K_0201_1%  [R_0201]  26.63 28.26 0 bottom
RPD93  0_0402_5%  [R0402_0OHM]  261.27 30 90 top
RPD96  0_1206_5%  [R_1206]  262.41 33.22 180 bottom
RPD97  0_0201_5%  [R0201_0OHM]  257.35 41.15 180 top
RPD99  100K_0201_1%  [R_0201]  268.14 33.62 180 top
RPD100  100K_0201_1%  [R_0201]  22.84 31.28 0 top
RPD101  300K_0201_1%  [R_0201]  261.95 31.36 270 top
RPD102  100K_0201_1%  [R_0201]  262.52 30.78 90 top
RPD105  0_0201_5%  [R0201_0OHM]  264.55 43.76 90 top
RPD106  0_0201_5%  [R0201_0OHM]  263.92 43.76 90 top
RPD109  0_0201_5%  [R0201_0OHM]  266.07 43.74 90 top
RPD112  0_0201_5%  [R0201_0OHM]  27.12 41.39 90 bottom
RPD113  0_0201_5%  [R0201_0OHM]  263.28 43.76 90 top
RPD121  0_1206_5%  [R_1206]  33.02 28.47 90 bottom
RPD123  0_0201_5%  [R0201_0OHM]  33.16 41.92 270 bottom
RPD124  0_0201_5%  [R0201_0OHM]  22.41 33.5 0 bottom
RPD126  0_0201_5%  [R0201_0OHM]  24.97 41.99 270 bottom
RPD127  0_0201_5%  [R0201_0OHM]  30.3 41.92 270 bottom
RPD128  100K_0201_5%  [R_0201]  30.87 41.92 270 bottom
RPD129  10K_0201_5%  [R_0201]  31.44 41.92 270 bottom
RPD130  0_0201_5%  [R0201_0OHM]  33.63 39.39 180 bottom
RPD131  0_0201_5%  [R_0201]  268.15 38.56 180 top
RPD132  0_0201_5%  [R0201_0OHM]  267.99 35.84 180 top
RPD134  0_0201_5%  [R0201_0OHM]  265.43 44.33 270 top
RPD135  0_0201_5%  [R0201_0OHM]  260.1 44.26 270 top
RPD136  100K_0201_5%  [R_0201]  259.53 44.26 270 top
RPD137  10K_0201_5%  [R_0201]  258.96 44.26 270 top
RPD138  0_0201_5%  [R0201_0OHM]  256.77 41.79 0 top
RPD139  0_0201_5%  [R_0201]  33.05 36.16 0 bottom
RPD141  0_0201_5%  [R_0201]  33.05 40.03 0 bottom
RPD142  0_0201_5%  [R_0201]  22.41 35.09 0 bottom
RPD144  0_0201_5%  [R_0201]  257.35 38.5 180 top
RPD146  0_0201_5%  [R_0201]  267.99 37.43 180 top
RPD147  0_0201_5%  [R_0201]  256.77 39.49 0 top
RPD155  0_0201_5%  [R_0201]  22.25 36.22 0 bottom
RPD157  0_0201_5%  [R0201_0OHM]  257.24 44.26 270 top
RPD163  0_0201_5%  [R0201_0OHM]  22.9 39.39 180 bottom
RPD164  0_0201_5%  [R0201_0OHM]  22.9 40.03 180 bottom
RPD165  0_0201_5%  [R0201_0OHM]  267.5 41.41 0 top
RPD166  0_0201_5%  [R0201_0OHM]  267.5 41.99 0 top
RPD167  1M_0201_5%  [R_0201]  267.99 35.27 180 top
RPD168  10K_0201_5%  [R_0201]  267.99 34.7 180 top
RPD169  1M_0201_5%  [R_0201]  22.41 32.93 0 bottom
RPD170  10K_0201_5%  [R_0201]  22.41 32.36 0 bottom
RPD171  0_0201_5%  [R0201_0OHM]  256.77 37.29 0 top
RPD172  0_0201_5%  [R0201_0OHM]  33.63 34.31 180 bottom
RPD173  0_0201_5%  [R_0201]  256.77 36.66 0 top
RPD174  0_0201_5%  [R_0201]  33.63 34.95 180 bottom
RPD177  100K_0201_5%  [R_0201]  257.35 36.02 180 top
RPD181  10K_0201_5%  [R_0201]  28.9 41.97 270 bottom
RPD182  10K_0201_5%  [R_0201]  261.51 44.32 270 top
RPD183  10K_0201_5%  [R_0201]  32.02 41.92 270 bottom
RPD184  10K_0201_5%  [R_0201]  258.39 44.26 270 top
RPD185  0_0201_5%  [R0201_0OHM]  29.67 42.56 270 bottom
RPD186  0_0201_5%  [R0201_0OHM]  260.74 44.9 270 top
RPD187  0_0201_5%  [R0201_0OHM]  24.01 30.64 180 bottom
RPD188  0_0201_5%  [R0201_0OHM]  266.39 32.99 0 top
RPD189  10K_0201_5%  [R_0201]  33.05 33.68 0 bottom
RPD190  100K_0201_5%  [R_0201]  23.43 31.28 0 bottom
RPD191  100K_0201_5%  [R_0201]  33.73 41.34 90 bottom
RPD192  100K_0201_5%  [R_0201]  256.67 43.68 90 top
RPD193  100K_0201_5%  [R_0201]  266.97 33.62 180 top
RPD194  0_0201_5%  [R_0201]  22.41 34.52 0 bottom
RPD199  0_0201_5%  [R_0201]  267.99 36.86 180 top
RPD204  0_0201_5%  [R_0201]  33.05 35.6 0 bottom
RPD205  0_0201_5%  [R_0201]  257.35 37.94 180 top
RR1  6.2K_0402_1%  [R_0402]  7.53 44.98 0 bottom
RR2  0_0201_5%  [R0201_0OHM]  15.76 45.19 0 bottom
RR3  0_0201_5%  [R0201_0OHM]  15.76 44.56 0 bottom
RR4  0_0201_5%  [R0201_0OHM]  15.76 43.8 0 bottom
RR6  0_0201_5%  [R0201_0OHM]  15.76 42.53 0 bottom
RR8  0_0201_5%  [R0201_0OHM]  15.76 41.89 0 bottom
RR9  0_0201_5%  [R0201_0OHM]  15.76 41.26 0 bottom
RR10  10K_0201_1%  [R_0201]  12.76 37.83 90 bottom
RR11  10K_0201_1%  [R_0201]  11.86 37.38 180 bottom
RR12  0_0201_5%  [R0201_0OHM]  10.69 38.7 270 bottom
RS200  0_0603_5%  [R0603_0OHM]  180 5.78 0 top
RS207  0_0201_5%  [R0201_0OHM]  191.52 20.77 180 bottom
RS208  0_0201_5%  [R0201_0OHM]  191.52 21.4 180 bottom
RS377  10K_0201_5%  [R_0201]  176.59 8.73 0 top
RS379  0_0402_5%  [R0402_0OHM]  180.79 6.8 180 top
RS380  10K_0201_5%  [R_0201]  173.75 28.87 0 bottom
RS381  0_0402_5%  [R_0402]  176.54 7.99 0 top
RS382  0_0402_5%  [R_0402]  178.02 29.02 0 bottom
RS383  10K_0201_5%  [R_0201]  190.93 23.94 0 bottom
RS384  0_0201_5%  [R0201_0OHM]  190.93 24.58 0 bottom
RT1  1M_0201_1%  [R_0201]  23.06 54.48 0 top
RT2  1M_0201_1%  [R_0201]  22.82 52.61 0 top
RT3  1M_0201_1%  [R_0201]  261.71 52.78 180 bottom
RT4  1M_0201_1%  [R_0201]  261.71 52.2 180 bottom
RT6  10K_0201_5%  [R_0201]  30.4 60.45 180 bottom
RT7  100_0201_1%  [R_0201]  31.45 51.03 90 bottom
RT8  10K_0201_5%  [R_0201]  35.85 49.02 0 bottom
RT9  10K_0201_5%  [R_0201]  35.14 49.02 180 bottom
RT10  100K_0201_5%  [R_0201]  35.14 45.52 180 bottom
RT11  10K_0201_5%  [R_0201]  35.14 48.44 180 bottom
RT12  10K_0201_5%  [R_0201]  35.85 48.44 0 bottom
RT13  10K_0201_5%  [R_0201]  35.85 46.1 0 bottom
RT14  10K_0201_5%  [R_0201]  35.14 46.1 180 bottom
RT15  10K_0201_5%  [R_0201]  34.52 44.31 90 bottom
RT16  10K_0201_5%  [R_0201]  37.03 46.1 90 bottom
RT17  10K_0201_5%  [R_0201]  35.14 46.69 180 bottom
RT18  10K_0201_5%  [R_0201]  35.85 46.69 0 bottom
RT19  4.75K_0402_0.5%  [R_0402]  26.04 55.09 270 top
RT20  2.2K_0201_1%  [R_0201]  27.74 67.76 0 bottom
RT21  2.2K_0201_1%  [R_0201]  27.74 67 0 bottom
RT22  3.32K_0201_1%  [R_0201]  27.74 65.22 0 bottom
RT23  3.32K_0201_1%  [R_0201]  17.24 66.96 90 bottom
RT30  100_0201_1%  [R_0201]  271.15 47.74 90 bottom
RT33  100K_0201_5%  [R_0201]  272.5 54.26 0 bottom
RT34  10K_0201_5%  [R_0201]  272.5 53.68 0 bottom
RT35  10K_0201_5%  [R_0201]  272.5 53.11 0 bottom
RT36  10K_0201_5%  [R_0201]  272.17 47.44 0 bottom
RT37  10K_0201_5%  [R_0201]  272.17 48 0 bottom
RT38  10K_0201_5%  [R_0201]  272.17 48.56 0 bottom
RT39  10K_0201_5%  [R_0201]  272.17 49.12 0 bottom
RT40  10K_0201_5%  [R_0201]  272.17 49.67 0 bottom
RT41  10K_0201_5%  [R_0201]  272.17 50.23 0 bottom
RT42  2.2K_0201_1%  [R_0201]  281.14 42.38 0 bottom
RT43  2.2K_0201_1%  [R_0201]  280 42.38 180 bottom
RT44  3.32K_0201_1%  [R_0201]  278.47 42.38 180 bottom
RT45  3.32K_0201_1%  [R_0201]  280.38 52.39 0 bottom
RT50  4.75K_0402_0.5%  [R_0402]  265.3 52.05 270 top
RT53  0_0201_5%  [R_0201]  23.92 57.32 180 bottom
RT54  0_0201_5%  [R_0201]  22.12 57.32 0 bottom
RT55  0_0201_5%  [R_0201]  263.31 55.26 180 bottom
RT56  0_0201_5%  [R_0201]  263.31 54.7 180 bottom
RT59  0_0201_5%  [R0201_0OHM]  35.14 49.61 180 bottom
RT62  0_0201_5%  [R0201_0OHM]  271.87 48.96 270 top
RT63  10K_0201_5%  [R_0201]  29.41 51.55 180 top
RT64  10K_0201_5%  [R_0201]  29.24 53.18 180 top
RT65  10K_0201_5%  [R_0201]  29.41 50.95 180 top
RT71  10K_0201_5%  [R_0201]  269.39 45.79 180 bottom
RT72  10K_0201_5%  [R_0201]  268.44 48.71 270 top
RT73  10K_0201_5%  [R_0201]  269.08 48.71 270 top
RT79  0_0402_5%  [R0402_0OHM]  26.73 47.03 180 bottom
RT83  0_0201_5%  [R0201_0OHM]  23.13 49 270 bottom
RT84  0_0201_5%  [R_0201]  23.74 49 270 bottom
RT88  0_0402_5%  [R0402_0OHM]  260.61 49.74 90 bottom
RT93  100K_0201_5%  [R_0201]  256.63 52.39 0 top
RT94  0_0201_5%  [R0201_0OHM]  255.36 52.52 270 top
RT95  0_0201_5%  [R_0201]  254.73 52.52 270 top
RT97  10K_0201_5%  [R_0201]  29.41 52.14 180 top
RT98  10K_0201_5%  [R_0201]  272.38 46.22 0 bottom
RT101  0_0201_5%  [R_0201]  29.82 59.87 0 bottom
RT102  0_0201_5%  [R_0201]  270.6 56.54 0 bottom
RT109  10K_0201_5%  [R_0201]  30.99 60.45 270 bottom
RT112  0_0201_5%  [R0201_0OHM]  25.08 51.04 90 bottom
RT113  0_0201_5%  [R0201_0OHM]  25.66 51.04 90 bottom
RT116  0_0201_5%  [R0201_0OHM]  263.36 53.24 0 bottom
RT117  0_0201_5%  [R0201_0OHM]  263.36 53.88 0 bottom
RT118  1M_0201_1%  [R_0201]  10.85 67.12 0 top
RT119  1M_0201_1%  [R_0201]  10.16 67.12 180 top
RT120  1M_0201_1%  [R_0201]  275.35 57.47 270 bottom
RT121  1M_0201_1%  [R_0201]  275.35 58.11 90 bottom
RT122  0_0201_5%  [R_0201]  26.84 55.78 180 top
RT123  0_0201_5%  [R_0201]  267.3 51.97 0 top
RT124  0_0201_5%  [R0201_0OHM]  30.32 57.18 0 top
RT125  0_0201_5%  [R0201_0OHM]  30.32 56.54 0 top
RT150  1M_0201_1%  [R_0201]  30.95 22.57 0 bottom
RT151  1M_0201_1%  [R_0201]  259.45 24.91 180 top
RT152  0_0201_5%  [R0201_0OHM]  21.17 56.22 0 bottom
RT158  10K_0201_5%  [R_0201]  256 51.88 90 top
RT159  0_0201_5%  [R_0201]  35.85 47.86 0 bottom
RT160  0_0201_5%  [R_0201]  35.85 47.27 0 bottom
RT162  0_0201_5%  [R_0201]  35.85 49.61 0 bottom
RT163  0_0201_5%  [R_0201]  272.45 48.39 270 top
RT164  0_0201_5%  [R0201_0OHM]  22.82 53.88 0 top
RT165  0_0201_5%  [R0201_0OHM]  22.82 53.24 0 top
RT166  0_0201_5%  [R0201_0OHM]  259.93 52.2 0 bottom
RT167  0_0201_5%  [R0201_0OHM]  259.93 52.78 0 bottom
RT168  0_0201_5%  [R0201_0OHM]  29.19 47.33 180 bottom
RT169  0_0201_5%  [R_0201]  31.42 63.82 0 bottom
RT170  0_0201_5%  [R_0201]  249.18 24.15 180 bottom
RT171  0_0201_5%  [R0201_0OHM]  260.57 47.44 90 bottom
RT172  10K_0201_5%  [R_0201]  35.85 45.52 0 bottom
RT173  10K_0201_5%  [R_0201]  272.5 54.83 0 bottom
RT175  0_0201_5%  [R_0201]  265.18 56.58 180 bottom
RT176  0_0201_5%  [R_0201]  28.97 49.76 90 top
RT177  0_0201_5%  [R_0201]  272.38 45.66 0 bottom
RT178  100K_0201_5%  [R_0201]  21.91 48.42 90 bottom
RT179  10K_0201_5%  [R_0201]  22.52 48.42 90 bottom
RT180  0_0402_5%  [R0402_0OHM]  30.4 55.78 0 top
RT181  0_0402_5%  [R0402_0OHM]  30.4 54.95 0 top
RT184  0_0402_5%  [R0402_0OHM]  259.84 50.65 270 bottom
RT185  0_0402_5%  [R0402_0OHM]  261.37 50.65 270 bottom
RT186  0_0201_5%  [R_0201]  31.56 60.45 270 bottom
RT187  0_0201_5%  [R_0201]  272.39 46.86 0 top
RT189  10K_0201_5%  [R_0201]  272.5 55.4 0 bottom
RT190  10K_0201_5%  [R_0201]  272.5 55.97 0 bottom
RT193  100K_0201_5%  [R_0201]  35.14 47.86 180 bottom
RT194  100K_0201_5%  [R_0201]  35.14 47.27 180 bottom
RT195  100K_0201_5%  [R_0201]  272.25 51.4 0 bottom
RT196  100K_0201_5%  [R_0201]  272.25 51.97 0 bottom
RT197  0_0201_5%  [R0201_0OHM]  270.75 52.3 270 top
RT198  0_0201_5%  [R0201_0OHM]  270.17 52.29 270 top
RT199  0_0201_5%  [R0201_0OHM]  272.25 56.54 0 bottom
RT200  0_0201_5%  [R_0201]  272.25 52.54 0 bottom
RT201  0_0201_5%  [R_0201]  272.25 50.83 0 bottom
RT202  0_0201_5%  [R_0201]  258.95 51.75 270 bottom
RT203  0_0201_5%  [R_0201]  21.16 55.59 0 bottom
RT218  10K_0201_5%  [R_0201]  30.78 54.27 0 top
RT219  10K_0201_5%  [R_0201]  272.26 46.88 0 bottom
RT224  10K_0201_5%  [R_0201]  262.47 56.51 180 bottom
RT225  100K_0201_5%  [R_0201]  261.28 56.51 180 bottom
RT226  10K_0201_5%  [R_0201]  25.54 57.57 270 top
RT227  0_0201_5%  [R_0201]  25.88 59.73 180 top
RT228  100K_0201_5%  [R_0201]  24.91 57.57 270 top
RTCD2  -  [LBAT54HT1G_SOD323-2]  8.29 40.63 270 bottom
RTCD3  -  [RB520SM-30T2R_EMD2-2]  5.91 42.59 90 bottom
RTCD4  -  [LBAT54HT1G_SOD323-2]  4.99 40.63 270 bottom
RTCD5  -  [LBAT54HT1G_SOD323-2]  6.64 40.63 270 bottom
RTCR4  100K_0201_5%  [R_0201]  197.3 22.57 180 bottom
RV75  2A_65V_T0603FF2000TM  [F_T0603FF1000TM]  167.43 62.58 90 top
RW1  2.2K_0201_5%  [R_0201]  257.61 15.79 180 top
RW6  0_0402_5%  [R_0402]  255.23 17.19 90 top
RW7  0_0402_5%  [R_0402]  254.45 17.19 90 top
RW8  0_0201_5%  [R_0201]  254.29 19.56 90 top
RW13  0_0201_5%  [R_0201]  259.53 13.99 90 top
RW17  0_0201_5%  [R_0201]  264.38 18.74 180 bottom
RW19  100K_0201_5%  [R_0201]  264.54 20.46 180 bottom
RW28  22_0201_1%  [R_0201]  255.8 10.81 0 top
RW29  100K_0201_1%  [R_0201]  257.46 14.04 180 top
RW30  4.7K_0201_5%  [R_0201]  257.46 14.65 180 top
RW31  22_0201_1%  [R_0201]  254.84 10.81 180 top
RW32  10K_0201_5%  [R_0201]  257.58 12.08 180 top
RW33  20K_0201_5%  [R_0201]  257.58 11.47 180 top
RW39  2.2K_0201_5%  [R_0201]  261.2 16.32 0 top
RW40  2.2K_0201_5%  [R_0201]  261.2 16.96 0 top
RW43  2.2K_0201_5%  [R_0201]  257.82 17.2 270 top
RW45  0_0201_5%  [R_0201]  261.79 15.56 180 top
RW46  0_0201_5%  [R_0201]  264.55 21.1 180 bottom
RW47  0_0201_5%  [R_0201]  261.58 22.4 270 bottom
RW52  4.7K_0201_5%  [R_0201]  267.32 9.07 270 top
RW53  10K_0201_5%  [R_0201]  173.47 46.83 180 bottom
RW54  0_0201_5%  [R_0201]  263.08 18.18 180 top
RW55  10K_0201_5%  [R_0201]  246.99 10.51 0 bottom
RW56  10K_0201_5%  [R_0201]  246.99 11.09 0 bottom
RW57  100K_0201_1%  [R_0201]  264.67 18.18 0 top
RW58  100K_0201_1%  [R_0201]  260.47 10.17 270 top
RW59  10K_0201_5%  [R_0201]  189.83 14.8 180 top
RW126  0_0402_5%  [R0402_0OHM]  239.69 3.22 270 bottom
RW127  0_0402_5%  [R0402_0OHM]  242.23 3.22 270 bottom
RW128  0_0402_5%  [R0402_0OHM]  244.77 3.22 270 bottom
RW226  1M_0201_5%  [R_0201]  263.87 9.05 270 top
RW227  1M_0201_5%  [R_0201]  264.48 8.46 90 top
RW1233  0_0402_5%  [R_0402]  259.42 12.18 90 top
RW1234  1K_0201_5%  [R_0201]  263.26 8.46 90 top
RW1235  0_0201_5%  [R_0201]  267.27 12.24 0 top
RW1236  0_0201_5%  [R_0201]  267.29 12.92 0 top
RW1237  0_0402_5%  [R0402_0OHM]  247.31 3.22 270 bottom
RW1238  0_0402_5%  [R0402_0OHM]  249.85 2.3 90 bottom
RW1240  0_0201_5%  [R_0201]  260.69 11.37 180 top
RW1241  0_0201_5%  [R_0201]  264.05 15.77 90 top
RZ1  0_0603_5%  [R0603_0OHM]  106.26 71.1 90 bottom
RZ2  0_0402_5%  [R0402_0OHM]  173.32 7.18 0 top
SW1  SKSFABE010_4P  [SW_SKSFABE010_4P]  241.39 9.49 270 bottom
TP3  PAD~D  [TPC12]  150.64 53.56 180 top
TP4  PAD~D  [TPC12]  151.81 54.11 180 top
TP6A4  PAD~D  [TPC12]  25.16 59.48 90 bottom
TP6A5  PAD~D  [TPC12]  264.96 55.14 0 top
TP7  PAD~D  [TPC12]  124.09 52.44 180 top
TP8  PAD~D  [TPC12]  125.41 52.98 180 top
TP15  PAD~D  [TPC12]  162.98 54.96 180 top
TP16  PAD~D  [TPC12]  157.72 45.92 180 top
TP17  PAD~D  [TPC12]  173.93 58.92 0 bottom
TP18  PAD~D  [TPC12]  129.5 60.82 0 bottom
TP19  PAD~D  [TPC12]  173.7 60.37 0 bottom
TP23  PAD~D  [TPC12]  173.88 35.1 0 bottom
TP24  PAD~D  [TPC12]  174.21 33.8 0 bottom
TP45  PAD~32  [TPC32]  31.99 52.8 0 top
TP46  PAD~32  [TPC32]  30.7 53.2 0 top
TP47  PAD~32  [TPC32]  31.65 51.51 0 top
TP48  PAD~32  [TPC32]  30.34 51.84 0 top
TP49  PAD~D  [TPC12]  270.04 46.6 180 bottom
TP50  PAD~32  [TPC32]  266.92 48.58 180 top
TP51  PAD~D  [TPC12]  271.06 44.87 0 top
TP52  PAD~32  [TPC32]  270.09 50.36 180 top
TP58  PAD~D  [TPC12]  180.99 26.13 0 top
TP59  PAD~D  [TPC12]  120.03 61.89 0 bottom
TP60  PAD~D  [TPC12]  121.32 61.92 0 bottom
TP61  PAD~D  [TPC12]  143.65 52.9 180 top
TP62  PAD~D  [TPC12]  145.1 54.4 180 top
TP63  PAD~D  [TPC12]  146.06 55.49 180 top
TP64  PAD~D  [TPC12]  143.47 54.17 180 top
TP65  PAD~D  [TPC12]  162.14 45.72 180 top
TP66  PAD~D  [TPC12]  162.2 44.19 180 top
TP67  PAD~D  [TPC12]  124.92 42.29 180 top
TP68  PAD~D  [TPC12]  127.67 41.88 180 top
TP69  PAD~D  [TPC12]  124.8 57.73 180 top
TP71  PAD~D  [TPC12]  132.9 42.76 180 top
TP72  PAD~D  [TPC12]  130.46 41.97 180 top
TP73  PAD~D  [TPC12]  131.59 42.61 180 top
TP74  PAD~D  [TPC12]  188.35 15.26 0 top
TP84  PAD~D  [TPC12]  182.31 9.26 0 top
TP88  PAD~D  [TPC12]  129.22 42.46 180 top
TP89  PAD~D  [TPC12]  136.77 55.62 180 top
TP90  PAD~D  [TPC12]  135.9 54.68 180 top
TP91  PAD~D  [TPC12]  142.2 52.85 180 top
TP92  PAD~D  [TPC12]  155.51 45.71 180 top
TP93  PAD~D  [TPC12]  137.15 54.32 180 top
TP94  PAD~D  [TPC12]  146.67 54.3 180 top
TP95  PAD~D  [TPC12]  126.23 42.33 180 top
TP96  PAD~D  [TPC12]  161.49 53.45 180 top
TP97  PAD~D  [TPC12]  156.63 45 180 top
TP98  PAD~D  [TPC12]  158.03 44.65 180 top
TP99  PAD~D  [TPC12]  126.34 58.04 180 top
TP100  PAD~D  [TPC12]  163.4 45.4 270 top
TP101  PAD~D  [TPC12]  162.32 31.82 0 bottom
TP110  PAD~D  [TPC12]  28.82 22.01 180 bottom
TP111  PAD~D  [TPC12]  262.09 21.85 270 top
TP115  PAD~50  [TPC20]  130.39 66.51 0 top
TP116  PAD~50  [TPC20]  136.64 63.85 0 top
TP117  PAD~50  [TPC20]  137.38 64.97 0 top
TP118  PAD~50  [TPC20]  133.08 61.36 180 bottom
TP119  PAD~50  [TPC20]  136.34 60.24 0 top
TP120  PAD~50  [TPC20]  135.04 65.32 0 top
TP121  PAD~50  [TPC20]  129.22 67.07 0 top
TP122  PAD~50  [TPC20]  127.88 64.99 0 top
TP123  PAD~50  [TPC20]  128.51 59.91 0 top
TP124  PAD~50  [TPC20]  126.25 61.82 0 top
TP125  PAD~50  [TPC20]  126.02 66.51 0 top
